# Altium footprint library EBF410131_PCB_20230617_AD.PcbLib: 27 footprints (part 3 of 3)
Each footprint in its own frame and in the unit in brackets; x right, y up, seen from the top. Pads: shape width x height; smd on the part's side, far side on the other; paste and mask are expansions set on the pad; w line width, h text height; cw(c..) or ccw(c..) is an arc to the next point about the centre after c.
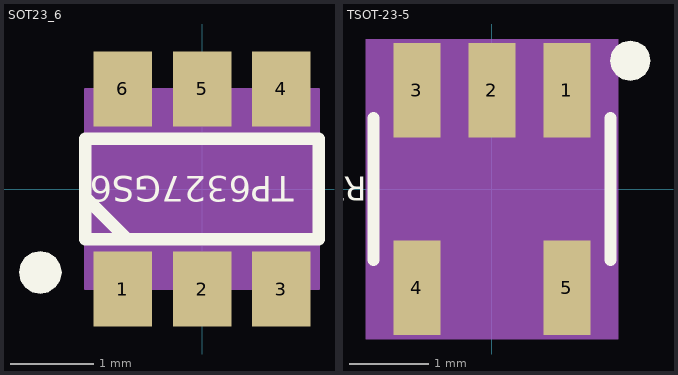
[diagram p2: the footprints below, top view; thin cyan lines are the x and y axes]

## SOT23_6 [mm] "SOT23_6"
pads (6):
  rect 0.7x0.9 smd: 1(-0.95,-1.2) 2(0,-1.2) 3(0.95,-1.2) 4(0.95,1.2) 5(0,1.2) 6(-0.95,1.2)
Top Overlay:
  dashed: -2.195,-1 -2.176,-1.098 -2.12,-1.18 -2.038,-1.236 -1.94,-1.255 -1.842,-1.236 -1.815,-1.217 -1.76,-1.18 -1.704,-1.098 -1.685,-1 -1.704,-0.902 -1.76,-0.82 -1.815,-0.783 -1.842,-0.764 -1.94,-0.745 -2.038,-0.764 -2.12,-0.82 -2.176,-0.902
  lines w0.15: -1.4,-0.1 -0.9,-0.6 ; -1.4,-0.6 1.4,-0.6 1.4,0.6 -1.4,0.6 -1.4,-0.6
  text "TP6327GS6" at 1.097,0.152 h0.3
Top 3D Body:
  region: -1.4,-1.2 1.4,-1.2 1.4,1.2 -1.4,1.2
Mechanical 12:
  text "3" at 1.204,-1.2 h0.64
  text "1" at -0.696,-1.2 h0.64
  text "6" at -0.696,1.2 h0.64
  text "5" at 0.254,1.2 h0.64
  text "2" at 0.254,-1.2 h0.64
  text "4" at 1.204,1.2 h0.64
Top Assembly:
  lines w0.025: -1.4,-1.2 -1.4,1.2 1.4,1.2 1.4,-1.2 -1.4,-1.2
3D body: height 3.81, standoff 0, extent -1.4,-1.2 1.4,1.2

## TSOT-23-5 [mm] "TSOT-23-5"
pads (5):
  rect 0.599x1.199 smd: 1(0.95,1.25) 2(0,1.25) 3(-0.95,1.25) 4(-0.95,-1.25) 5(0.95,-1.25)
Top Overlay:
  dashed: 2.008,1.626 1.988,1.528 1.933,1.445 1.85,1.39 1.753,1.371 1.655,1.39 1.627,1.409 1.572,1.445 1.517,1.528 1.498,1.626 1.517,1.723 1.572,1.806 1.627,1.843 1.655,1.861 1.753,1.88 1.85,1.861 1.933,1.806 1.988,1.723
  lines w0.15: -1.5,-0.9 -1.5,0.9 ; 1.5,-0.9 1.5,0.9
  text "RT8097CHGB/NC" at -1.585,0.152 h0.3
Top 3D Body:
  region: 1.6,-1.9 1.6,1.9 -1.6,1.9 -1.6,-1.9
Mechanical 12:
  text "4" at -0.99,-1.25 h0.1
  text "3" at -0.99,1.25 h0.1
  text "5" at 0.91,-1.25 h0.1
  text "1" at 0.91,1.25 h0.1
  text "2" at -0.04,1.25 h0.1
Top Assembly:
  lines w0.15: -1.5,-0.85 -1.5,0.85 1.5,0.85 1.5,-0.85 -1.5,-0.85
3D body: height 3.81, standoff 0, extent -1.6,-1.9 1.6,1.9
